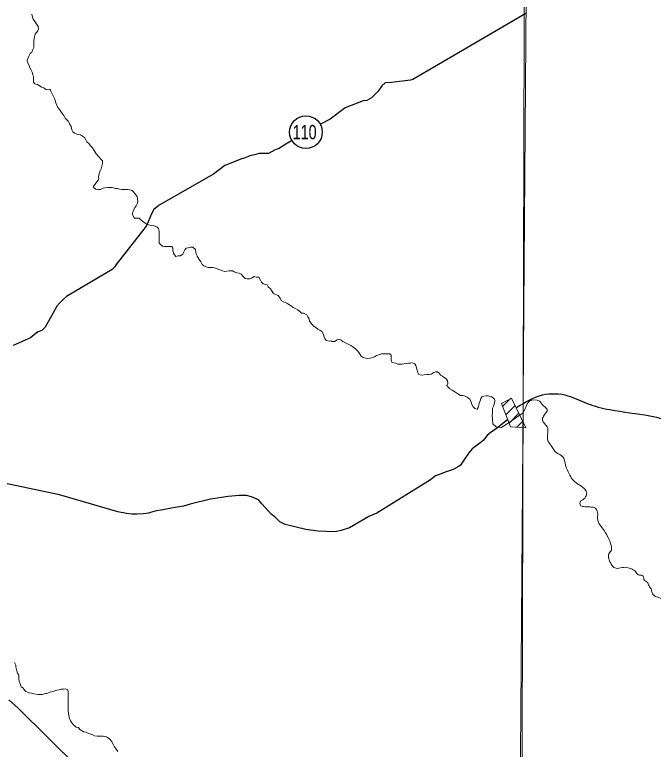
# Model space of a CAD drawing. Extents: x 553962 to 842807, y 8883888 to 9032388.
# Drawn here: x 616027 to 619158, y 8902830 to 8906430 of the extents above; entities that cross this region are included whole.
import ezdxf
from ezdxf.enums import TextEntityAlignment as Align

# ---------------------------------------------------------------- set-up
doc = ezdxf.new("R2010")
doc.units = 0
doc.header["$LTSCALE"] = 200
doc.layers.add('6', color=7, linetype='Continuous', lineweight=13)

msp = doc.modelspace()

# ---------------------------------------------------------------- linework, layer by layer
at = {"layer": '6'}
for p, q in [((618419.3, 8904510), (618459.5, 8904550.2)), ((618435.1, 8904469.2), (618480.5, 8904514.6)), ((618451, 8904428.5), (618499.1, 8904476.6)), ((618488.1, 8904409.1), (618517.7, 8904438.6))]:
    msp.add_line(p, q, dxfattribs=at)
for points in [[(618663, 8924716.1), (618558.3, 8909803.7), (618456.5, 8896026.7)], [(616110.9, 8906433.2), (616113.9, 8906417.9), (616117.9, 8906407.7), (616124.9, 8906396.4), (616133, 8906387.2), (616142.1, 8906372.9), (616144, 8906360.7), (616139.9, 8906350.5), (616133.7, 8906342.4), (616127.6, 8906334.3), (616123.4, 8906322.1), (616120.2, 8906304.8), (616120.1, 8906290.5), (616120.1, 8906279.3), (616120, 8906269.1), (616114.8, 8906256.9), (616110.7, 8906246.8), (616102.5, 8906239.7), (616096.3, 8906227.5), (616092.2, 8906218.4), (616088, 8906208.2), (616092, 8906192.9), (616098, 8906181.7), (616101, 8906170.4)], [(616101, 8906170.4), (616108, 8906159.2), (616112, 8906149), (616116, 8906136.7), (616119, 8906123.4), (616119.9, 8906110.2), (616119.8, 8906099), (616125.9, 8906090.8), (616138.1, 8906087.7), (616147.2, 8906083.5), (616158.3, 8906075.3), (616170.5, 8906072.2), (616179.6, 8906064), (616191.8, 8906061.9), (616201, 8906065.9), (616204, 8906055.7), (616211, 8906042.4), (616215, 8906033.2), (616223, 8906015.8), (616229, 8905998.5), (616233, 8905986.2), (616239, 8905975), (616245.1, 8905966.8), (616252.1, 8905959.6), (616257.2, 8905950.4), (616267.2, 8905936.1), (616274.3, 8905923.8), (616282.3, 8905914.6), (616291.4, 8905906.4), (616295.4, 8905896.2), (616303.5, 8905881.8), (616307.4, 8905865.5), (616312.5, 8905856.3), (616320.5, 8905849.1), (616332.7, 8905845), (616349, 8905840.8), (616359.1, 8905835.6)], [(616359.1, 8905835.6), (616369.2, 8905828.4), (616376.3, 8905817.2), (616380.3, 8905808), (616391.4, 8905797.7), (616400.5, 8905786.5), (616408.5, 8905777.2), (616416.6, 8905765), (616426.7, 8905748.6), (616438.8, 8905733.2), (616450.9, 8905720.9), (616458, 8905713.8), (616457.9, 8905701.6), (616453.7, 8905687.3), (616451.6, 8905675.1), (616445.4, 8905664.9), (616441.2, 8905651.7), (616438.2, 8905636.4), (616439.5, 8905627.9), (616437, 8905619.4), (616419.4, 8905598.1), (616413.4, 8905587.8), (616413.3, 8905582.6), (616424.5, 8905575.4), (616435.6, 8905574.3), (616447.8, 8905574.3), (616461.1, 8905580.3), (616469.2, 8905581.7), (616483.5, 8905583.2), (616495.7, 8905584.1), (616505.6, 8905583.6), (616520.7, 8905578.7), (616530.4, 8905578.1), (616540.1, 8905575.7), (616551, 8905573.2), (616566.8, 8905573.2), (616579.5, 8905573.2), (616589.8, 8905572), (616602.6, 8905568.4), (616607.5, 8905563.1), (616614.5, 8905555.9), (616620.6, 8905547.7), (616626.6, 8905538.5), (616629.6, 8905526.2), (616630.5, 8905514), (616627.4, 8905503.8), (616623.2, 8905493.7), (616616.5, 8905485.2), (616611.7, 8905474.3), (616606.2, 8905463.3), (616604.4, 8905455.4), (616605, 8905450), (616611.1, 8905437.2), (616614.7, 8905433.6), (616624.9, 8905433.6), (616637.1, 8905432.5), (616646.2, 8905423.2), (616659.3, 8905414), (616668.4, 8905406.8), (616679.6, 8905402.6), (616689.8, 8905398.5), (616699.9, 8905397.4), (616710.1, 8905395.3), (616724.3, 8905390.1), (616732.4, 8905382.9)], [(616732.4, 8905382.9), (616735.3, 8905369.7), (616735.3, 8905359.5), (616735.2, 8905344.2), (616735, 8905325.9), (616734.9, 8905312.6), (616742, 8905304.4), (616752.1, 8905295.2), (616762.3, 8905294.1), (616773.5, 8905294.1), (616784.7, 8905294), (616796.9, 8905294.9), (616802.9, 8905285.7), (616802.8, 8905275.5), (616804.8, 8905262.3), (616810.8, 8905254.1), (616816.9, 8905244.9), (616828.1, 8905247.9), (616838.2, 8905247.8), (616850.5, 8905255.9), (616856.7, 8905268.1), (616860.8, 8905277.2), (616867, 8905285.3), (616877.2, 8905288.3), (616890.4, 8905291.3), (616900.6, 8905291.2), (616912.7, 8905279.9), (616915.7, 8905266.7), (616916.6, 8905256.5), (616921.7, 8905246.2), (616931.7, 8905229.9), (616939.8, 8905218.6), (616945.8, 8905205.3), (616954.9, 8905199.2), (616965, 8905194), (616976.2, 8905190.9), (616986.4, 8905190.8)], [(616986.4, 8905190.8), (616996.5, 8905190.7), (617006.7, 8905189.7), (617018.9, 8905185.5), (617032.1, 8905179.3), (617046.3, 8905175.1), (617056.4, 8905172), (617067.6, 8905173), (617078.8, 8905174.9), (617094.1, 8905174.8), (617103.2, 8905169.7), (617116.4, 8905165.5), (617127.6, 8905163.4), (617137.7, 8905158.2), (617148.8, 8905144.9), (617156.9, 8905136.7), (617167.1, 8905135.7), (617179.3, 8905135.6), (617188.5, 8905139.6), (617200.7, 8905146.6), (617212.9, 8905144.5), (617223.1, 8905143.4), (617231.1, 8905132.2), (617237.1, 8905118.9), (617245.2, 8905110.7), (617255.4, 8905107.6), (617265.5, 8905106.5), (617269.5, 8905097.3), (617281.7, 8905086), (617289.7, 8905073.7), (617295.8, 8905064.5), (617304.9, 8905058.4), (617319.1, 8905054.2), (617329.2, 8905040.9), (617334.2, 8905029.7), (617345.3, 8905022.4), (617361.6, 8905016.2), (617371.7, 8905010.1), (617383.8, 8905001.8), (617392.9, 8904995.7), (617404.1, 8904990.5), (617415.2, 8904984.3), (617425.3, 8904975.1), (617432.4, 8904966.9), (617442.6, 8904966.8), (617458.8, 8904958.6), (617464.8, 8904949.3), (617469.9, 8904940.1), (617472.8, 8904927.9), (617483.6, 8904913.2), (617490, 8904906.8), (617490, 8904904.7), (617503.1, 8904897.1), (617513.3, 8904888.9), (617523.5, 8904884.2), (617532.9, 8904877.9), (617539.1, 8904867), (617542.2, 8904856.1), (617546.9, 8904843.6), (617554.7, 8904834.2), (617568.8, 8904829.5), (617576.6, 8904831.1), (617581.2, 8904827.9), (617594.2, 8904829.3), (617607.5, 8904836.4)], [(617607.5, 8904836.4), (617617.7, 8904839.4), (617627.8, 8904835.2), (617635.9, 8904829.1), (617649.1, 8904822.9), (617662.3, 8904815.6), (617674.4, 8904808.4), (617684.6, 8904802.2), (617695.7, 8904795.1), (617709.9, 8904780.7), (617716.9, 8904769.4), (617725, 8904757.2), (617736.1, 8904751), (617748.3, 8904746.8), (617758.4, 8904745.8), (617769.6, 8904746.7), (617781.9, 8904749.7), (617791.1, 8904753.7), (617800.2, 8904759.7), (617812.5, 8904763.7), (617824.7, 8904767.7), (617835.9, 8904768.7), (617855.2, 8904768.6), (617865.4, 8904768.5), (617872.5, 8904761.3), (617872.4, 8904748.1), (617872.3, 8904737.9), (617876.3, 8904727.7), (617885.5, 8904723.5), (617895.6, 8904722.4), (617904.7, 8904718.3), (617914.9, 8904718.2), (617925.1, 8904718.2), (617935.3, 8904719.1), (617957.7, 8904723.1), (617967.8, 8904723), (617979, 8904724)], [(617979, 8904724), (617989.2, 8904719.8), (617993.2, 8904710.6), (617998.2, 8904693.3), (618004.1, 8904676.9), (618008.2, 8904667.7), (618020.3, 8904663.6), (618034.6, 8904665.5), (618046.8, 8904667.5), (618057, 8904667.4), (618071.2, 8904668.3), (618078.4, 8904675.4), (618089.6, 8904679.4), (618099.8, 8904679.4), (618108.9, 8904672.2), (618114.9, 8904664), (618124.1, 8904658.8), (618132.2, 8904652.7), (618140.2, 8904646.5), (618148.3, 8904635.3), (618151.3, 8904625.1), (618146.1, 8904612.9), (618153.2, 8904603.6), (618160.2, 8904596.5), (618171.4, 8904589.3), (618184.6, 8904582.1), (618199.8, 8904572.8), (618212.9, 8904564.6), (618225.1, 8904563.4), (618235.3, 8904560.3), (618245.4, 8904556.2), (618257.6, 8904545.9), (618265.6, 8904531.6), (618267.5, 8904519.4), (618274.6, 8904508.1), (618283.7, 8904500.9), (618293.8, 8904496.8), (618300, 8904505.9), (618303.1, 8904516.1), (618304.2, 8904526.3), (618309, 8904537.8), (618312.5, 8904548.5), (618317.6, 8904556.7), (618326.8, 8904561.1), (618339.4, 8904562.8), (618348.3, 8904562.8), (618355.5, 8904561.1), (618364.4, 8904557.5), (618373.3, 8904552.1), (618378.7, 8904546.7), (618380.5, 8904539.6), (618381.6, 8904536), (618378.4, 8904521.7), (618374.3, 8904511.6), (618370.2, 8904501.4), (618370.1, 8904491.2), (618369, 8904479), (618367.9, 8904468.8), (618370.7, 8904425), (618386.8, 8904409.6), (618410.9, 8904405.3), (618427, 8904416), (618519.7, 8904479.2)], [(616025.4, 8903256.1), (616032.4, 8903242.8), (616031.9, 8903233.8), (616036.9, 8903215.3), (616040.3, 8903203.6), (616045.3, 8903196.9), (616047.3, 8903187.7), (616047.2, 8903175.5), (616048.1, 8903164.3), (616053.1, 8903151), (616058.1, 8903136.7), (616067.2, 8903131.6), (616077.1, 8903118.2), (616082.1, 8903113.2), (616097.1, 8903106.5)], [(616097.1, 8903106.5), (616110.5, 8903104.8), (616120.6, 8903101.5), (616142.3, 8903098.2), (616162.4, 8903098.2), (616179.1, 8903103.2), (616184.1, 8903103.2), (616189.1, 8903104.8), (616199.2, 8903109.9), (616207.5, 8903111.5), (616223.8, 8903117.3), (616234, 8903119.3), (616245.2, 8903121.3), (616254.4, 8903125.3), (616265.6, 8903125.2), (616276.8, 8903126.2), (616287.9, 8903121), (616288.8, 8903109.8), (616288.8, 8903098.6), (616288.7, 8903087.4), (616288.6, 8903076.2), (616288.5, 8903059.9), (616288.4, 8903040.5), (616288.3, 8903030.3), (616289.3, 8903020.1), (616291.2, 8903005.8), (616292.1, 8902994.6), (616295.1, 8902981.4), (616301.1, 8902969.1), (616307.2, 8902959.9), (616315.2, 8902949.7), (616327.9, 8902939.1), (616339.5, 8902936.3), (616346.3, 8902927.4), (616366.4, 8902915.6), (616378.1, 8902914), (616388.1, 8902907.3)], [(616388.1, 8902907.3), (616406.5, 8902902.2), (616418.2, 8902895.6), (616431.6, 8902893.9), (616441.7, 8902893.9), (616460.1, 8902893.9), (616476.8, 8902890.5), (616482.6, 8902888.5), (616493.8, 8902879.2), (616501.8, 8902870), (616510.9, 8902852.7), (616515.9, 8902842.4), (616524, 8902830.2), (616532, 8902818.9)]]:
    msp.add_lwpolyline(points, dxfattribs=at)
for points in [[(618535.2, 8909853.3), (607574.3, 8909890.7), (607543.3, 8898835.3), (618504.2, 8898795.8)], [(618462.3, 8904551.7), (618413.4, 8904525.1), (618457.8, 8904411), (618533.6, 8904406.1)]]:
    msp.add_lwpolyline(points, close=True, dxfattribs=at)
at = {"layer": '6', "lineweight": 25}
for points in [[(618533.2, 8906436.6), (617978.2, 8906112.6), (617967, 8906109.6), (617874.3, 8906097.6), (617843.7, 8906095.6), (617826.3, 8906081.3), (617808.9, 8906055.9), (617776.2, 8906022.3), (617753.7, 8906010.2), (617735.4, 8906008.2), (617647.6, 8905973.7), (617574.1, 8905917.8), (617526.6, 8905893.4)], [(617384.3, 8905811.9), (617340.2, 8905785.8), (617322.9, 8905774.6), (617304.5, 8905767.5), (617270.8, 8905750.2), (617226, 8905750.3), (617202.5, 8905743.2), (617180.1, 8905738.2), (617149.5, 8905726), (617144.4, 8905726), (617057.7, 8905690.5), (617001.5, 8905648.8), (616735, 8905497.5), (616708.4, 8905475.2), (616698.2, 8905454.8), (616689.9, 8905434.4), (616681.7, 8905415.1), (616671.4, 8905393.7), (616524, 8905206.5), (616515.8, 8905193.3), (616504.6, 8905181.1), (616281, 8905049.1), (616266.7, 8905035.8), (616248.2, 8905018.6), (616233.9, 8905002.3), (616214.4, 8904965.6), (616176.5, 8904899.5), (616160.1, 8904883.2), (616140.7, 8904876.1), (616105, 8904846.6), (616019.2, 8904809.1)], [(618442.8, 8904444.9), (618387.6, 8904401.3), (618365.2, 8904386.1), (618343.7, 8904367.8), (618323.2, 8904343.3), (618306.9, 8904331.1), (618288.5, 8904315.9), (618269.1, 8904302.7), (618252.7, 8904283.3), (618229.2, 8904247.7), (618212.8, 8904222.3), (618203.6, 8904215.2), (618177, 8904202), (618142.3, 8904189.8), (618104.6, 8904174.6), (618089.3, 8904169.5), (618064.8, 8904150.2), (617802.3, 8903987.7), (617762.5, 8903970.5), (617667.6, 8903914.6), (617626.8, 8903902.4), (617597.2, 8903896.4), (617513.6, 8903899.6), (617454.6, 8903907.9), (617406.7, 8903919.2), (617380.3, 8903925.3), (617352.8, 8903931.5), (617326.3, 8903944.8), (617302, 8903969.3), (617283.7, 8903982.5), (617271.5, 8903996.8), (617239, 8904033.6), (617221.8, 8904051.9), (617187.2, 8904067.3), (617162.8, 8904073.4), (617128.1, 8904074.5), (617074.1, 8904069.5), (616987.5, 8904055.4), (616887.5, 8904032.2), (616853.9, 8904022.1), (616803.9, 8904014), (616752.9, 8904003.9), (616713.2, 8903996.8), (616683.6, 8903987.7), (616658.1, 8903983.7), (616626.5, 8903981.7), (616602.1, 8903981.8), (616574.6, 8903984.9), (616532.8, 8903993.1), (616245.8, 8904077.2), (615725.6, 8904186.1)], [(615998.6, 8903072.1), (616044.3, 8903031.2), (616338.7, 8902741.3)]]:
    msp.add_lwpolyline(points, dxfattribs=at)
msp.add_circle((617454.9, 8905854.7), 80.3, dxfattribs=at)
msp.add_spline([(618487.4, 8904504.8), (618614.5, 8904566.7), (618739.5, 8904562.9), (618834.2, 8904525), (618944, 8904494.7), (619141, 8904464.4), (619269.8, 8904426.5), (619413.7, 8904347), (619610.7, 8904248.5), (619898.6, 8904070.5), (620175.1, 8903918.9), (620288.7, 8903884.9), (620489.5, 8903873.5), (620815.2, 8903858.3), (621019.8, 8903831.8), (621319, 8903718.2), (621610.7, 8903631.1), (621785, 8903608.3), (621841.8, 8903604.6), (621917.5, 8903551.5), (622012.2, 8903479.6), (622084.2, 8903426.5), (622194.1, 8903396.2), (622315.3, 8903388.6)], degree=3, dxfattribs=at)
at = {"layer": '6'}
msp.add_spline([(618519.7, 8904479.2), (618532.8, 8904506.8), (618550.3, 8904535.8), (618599.7, 8904535.8), (618620.1, 8904512.6), (618637.5, 8904495.1), (618620.1, 8904463.1), (618614.2, 8904442.8), (618637.5, 8904410.8), (618640.4, 8904378.8), (618640.4, 8904343.9), (618655, 8904320.7), (618684, 8904282.9), (618713.1, 8904265.4), (618727.6, 8904221.8), (618744.8, 8904180.8), (618762.3, 8904151.5), (618786.7, 8904131), (618818.9, 8904108.6), (618830.6, 8904091), (618828.7, 8904072.5), (618812.1, 8904053), (618800.4, 8904044.2), (618800.4, 8904026.6), (618815, 8904019.8), (618846.2, 8904017.8), (618874.5, 8904011), (618881.3, 8904002.2), (618885.2, 8903978.8), (618887.2, 8903945.6), (618897, 8903929), (618916.5, 8903901.7), (618940.9, 8903858.8), (618951.6, 8903826.6), (618952.6, 8903806.1), (618939.9, 8903788.6), (618938.9, 8903768.1), (618943.8, 8903752.4), (618951.6, 8903737.8), (618964.3, 8903721.2), (618988.7, 8903717.3), (619019.9, 8903722.2), (619047.2, 8903715.4), (619070.6, 8903701.7), (619085.3, 8903685.1), (619103.8, 8903681.2), (619110.6, 8903673.4), (619111.6, 8903661.7), (619127.2, 8903649.3), (619137, 8903630.8), (619146.7, 8903616.1), (619152.6, 8903596.6), (619164.3, 8903581.9), (619184.8, 8903573.2), (619214.1, 8903563.4)], degree=3, dxfattribs=at)

# ---------------------------------------------------------------- texts
at = {"layer": '6', "width": 0.75}
msp.add_text('110', height=70, dxfattribs=at).set_placement((617448.6, 8905820), align=Align.CENTER)

doc.saveas('drawing.dxf')
